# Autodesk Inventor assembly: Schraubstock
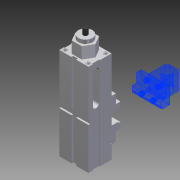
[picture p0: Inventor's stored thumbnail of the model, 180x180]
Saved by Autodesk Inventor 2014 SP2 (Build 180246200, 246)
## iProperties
Created: 2015-06
Part Number: Schraubstock
Document SubType Name: Assembly
Designer: e_krauts
Sending System: SolidWorks 2011
Last Author: e_boekem
Author: e_krauts
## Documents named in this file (6)
- Z:\VDW-Nachwuchsstiftung Intern\Mitarbeiter Ablage\Steffen Krauth\IVCAM\Schraubstock\Schraubstock.iam
- C:\Users\e_krauts\Downloads\Spannmittel\Schraubstock\Imported Components\Schraubstock\Backe20x40.ipt
- C:\Users\e_krauts\Downloads\Spannmittel\Schraubstock\Imported Components\Schraubstock\Unterteil.ipt
- C:\Users\e_krauts\Downloads\Spannmittel\Schraubstock\Imported Components\Schraubstock\Backe 40 x 20 ohne.ipt
- C:\Users\e_krauts\Downloads\Spannmittel\Schraubstock\Imported Components\Schraubstock\Spindel.ipt
- Z:\VDW-Nachwuchsstiftung Intern\Mitarbeiter Ablage\Steffen Krauth\IVCAM\Verteilerblock.ipt
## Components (5 placed, 5 different names)
1. Backe20x40:1 — Passend:2, Fluchtend:1, Passend:6, Passend:7, Fluchtend:2
2. Unterteil:1 — Passend:1, Passend:2, Passend:4, Passend:5, Fluchtend:1
3. Backe 40 x 20 ohne:1 — Passend:3, Passend:4, Passend:8
4. Spindel:2 — Passend:1, Passend:3, Passend:5
5. Verteilerblock:1 — Passend:6, Passend:7, Fluchtend:2, Passend:8
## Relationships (10: Mate 8, Flush 2)
- Passend:1 [Mate]: Unterteil:1 ↔ Spindel:2
- Passend:2 [Mate]: Backe20x40:1 ↔ Unterteil:1
- Passend:3 [Mate]: Backe 40 x 20 ohne:1 ↔ Spindel:2
- Passend:4 [Mate]: Unterteil:1 ↔ Backe 40 x 20 ohne:1
- Passend:5 [Mate]: Unterteil:1 ↔ Spindel:2
- Fluchtend:1 [Flush]: Backe20x40:1 ↔ Unterteil:1
- Passend:6 [Mate]: Backe20x40:1 ↔ Verteilerblock:1
- Passend:7 [Mate]: Backe20x40:1 ↔ Verteilerblock:1
- Fluchtend:2 [Flush]: Backe20x40:1 ↔ Verteilerblock:1
- Passend:8 [Mate]: Backe 40 x 20 ohne:1 ↔ Verteilerblock:1
